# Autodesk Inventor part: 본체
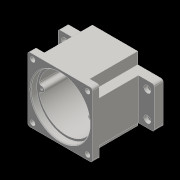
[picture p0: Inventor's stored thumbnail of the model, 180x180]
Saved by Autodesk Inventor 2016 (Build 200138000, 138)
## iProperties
Created: 2020-08
Part Number: 본체
Material: 일반
Document SubType Name: Modeling
Designer: User
Density: 1 g/cm^3
Appearance: 기본값
Author: User
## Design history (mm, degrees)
sketch "스케치1"
  geometry: L1 (47, 47)-(-47, 47); L2 (-47, 47)-(-47, -47); L3 (-47, -47)-(47, -47); L4 (47, -47)-(47, 47); L5 (47, 47)-(-47, -47); L6 (-47, 47)-(47, -47); 1 further point
  constraints: 12 end point, 2 midpoint, 2 parallel, 1 horizontal, 1 perpendicular
  dimensions: "d0" = 94 distance of L2.end L3.end; "d1" = 94 distance of L1.end L2.end
extrude "돌출1" new body sketch "스케치1" distance "d2" = 80; taper "d3" = 0 deg
sketch "스케치2"
  geometry: L1 (-70, -30)-(70, -30); L2 (70, -30)-(70, 30); L3 (70, 30)-(-70, 30); L4 (-70, 30)-(-70, -30); L5 (-70, -30)-(70, 30); L6 (70, -30)-(-70, 30); 1 further point
  constraints: 12 end point, 2 midpoint, 2 parallel, 1 horizontal, 1 perpendicular
  dimensions: "d4" = 60 distance of L1.end L2.end; "d5" = 140 distance of L2.end L3.end
extrude "돌출2" join sketch "스케치2" distance "d6" = 13; taper "d7" = 0 deg
sketch "스케치4"
  geometry: L1 (47, 47)-(-47, 47) reference; L2 (-47, 47)-(-33, 47); L3 (-33, 47)-(-33, 30); L4 (-33, 30)-(-47, 30); L5 (-47, 30)-(-47, 47); 1 further point
  constraints: 8 end point, 2 parallel, 1 horizontal, 1 perpendicular
  dimensions: "d8" = 17 distance of L2.end L3.end; "d9" = 14 distance of L3.end L4.end
extrude "돌출3" cut sketch "스케치4" distance "d10" = 70; taper "d11" = 0 deg
sketch "스케치5"
  geometry: L1 (-47, 47)-(-33, 47) reference; L2 (-47, 30)-(-47, 47) reference; C1 r 3.5 at (-40, 40); 1 further point
  constraints: 1 centre point
  dimensions: "d12" = 7 distance from line of L1 C1.centre; "d13" = 7 distance from line of C1.centre L2; "d14" = 7 diameter of C1
extrude "돌출4" cut sketch "스케치5" distance "d15" = 70; taper "d16" = 0 deg
sketch "스케치6"
  geometry: C1 r 27.5 at (0, 11); 1 further point
  constraints: 1 centre point, 1 vertical alignment
  dimensions: "d23" = 55 diameter of C1; "d24" = 11 distance of point (0, 0) C1.centre
extrude "돌출5" join sketch "스케치6" distance "d25" = 7; taper "d26" = 0 deg
sketch "스케치7"
  geometry: C1 r 27.5 at (0, 0) reference; C2 r 16 at (0, 0); 1 further point
  constraints: 1 centre point, 1 coincident
  dimensions: "d27" = 32 diameter of C2
extrude "돌출6" cut sketch "스케치7" distance "d28" = 9.1; taper "d29" = 0 deg
sketch "스케치8"
  geometry: C1 r 43 at (0, 0); 1 further point
  constraints: 1 centre point, 1 coincident
  dimensions: "d30" = 86 diameter of C1
extrude "돌출7" cut sketch "스케치8" distance "d31" = 9; taper "d32" = 0 deg
sketch "스케치9"
  geometry: C1 r 40 at (0, 0); 1 further point
  constraints: 1 centre point, 1 coincident
  dimensions: "d33" = 80 diameter of C1
extrude "돌출8" cut sketch "스케치9" distance "d34" = 62; taper "d35" = 0 deg
sketch "스케치10"
  geometry: C1 r 16 at (0, -11) reference; C2 r 21 at (0, -11); 1 further point
  constraints: 1 centre point, 1 coincident
  dimensions: "d36" = 42 diameter of C2
extrude "돌출9" join sketch "스케치10" distance "d37" = 7; taper "d38" = 0 deg
sketch "스케치11"
  geometry: L1 (-98, 0)-(98, 0) reference; L2 (0, -65.8)-(0, 65.8) reference; C1 r 15 at (0, 20); C2 r 21 at (0, -11) reference; 1 further point
  constraints: 1 centre point, 1 vertical alignment
  dimensions: "d39" = 20 distance from line of L1 C1.centre; "d40" = 30 diameter of C1
extrude "돌출10" join sketch "스케치11" distance "d41" = 7; taper "d42" = 0 deg
sketch "스케치15"
  geometry: L1 (-98, 0)-(98, 0) reference; L2 (0, -65.8)-(0, 65.8) reference; A1 r 4 centre (36, 0) between (36.19, 3.995) and (36.19, -3.995); A2 r 3 centre (36.333, -6.992) between (39.279, -7.559) and (36.19, -3.995); A3 r 3 centre (36.333, 6.992) between (36.19, 3.995) and (39.279, 7.559); A4 r 40 centre (0, 0) between (39.279, -7.559) and (39.279, 7.559) reference; 1 further point
  constraints: 8 point on circle, 5 tangent, 3 centre point, 1 horizontal alignment, 1 point on line
  dimensions: "d54" = 8 diameter of A1; "d55" = 6 diameter of A3; "d56" = 6 diameter of A2
extrude "돌출14" join sketch "스케치15" stored distance "d57" = 3; taper "d58" = 0 deg
sketch "스케치16"
  geometry: A1 r 4 centre (36, 0) between (36.19, 3.995) and (36.19, -3.995) reference; 2 further points
  constraints: 1 coincident
hole "구멍1" sketch "스케치16" at (36, 0) diameter "d59" = 3.242; stored, may be unused: countersink angle "d63" = 90 deg, drill point angle "d65" = 118 deg; dims "d60" = 7, "d61" = 4, "d62" = 2, "d64" = 9
sketch "스케치17"
  geometry: L1 (-98, 0)-(98, 0) reference; L2 (0, -65.8)-(0, 65.8) reference; L3 (47, -30)-(70, -30) reference; 3 further points
  dimensions: "d66" = 38 distance of point (60, 19) point (60, -19); "d67" = 60 distance from line of point (60, -19) L2; "d68" = 60 distance from line of L2 point (60, 19); "d69" = 11 distance from line of point (60, -19) L3
hole "구멍2" sketch "스케치17" at (60, -19), (60, 19) diameter "d70" = 4.5; stored, may be unused: countersink angle "d74" = 90 deg, drill point angle "d76" = 118 deg; dims "d71" = 7, "d72" = 10, "d73" = 5, "d75" = 20
chamfer "모따기1" distance "d77" = 0.8; stored, may be unused: second distance "d78" = 2, angle "d79" = 30 deg
fillet "모깎기1" dims "d83" = 3
chamfer "모따기5" distance "d91" = 1; stored, may be unused: second distance "d92" = 2, angle "d93" = 30 deg
sketch "스케치18"
  geometry: L1 (-77, -10)-(11, -10) reference; L2 (14, 57)-(14, 0) reference; 2 further points
  constraints: 1 other
  dimensions: "d94" = 40 distance from line of L1 point (-33, 30); "d95" = 47 distance from line of L2 point (-33, 30)
feature "엠보싱1" sketch "스케치18" dims "d96" = 0.5, "d97" = 0
sketch "스케치19"
  geometry: C1 r 17.5 at (0, -11); A1 r 21 centre (0, -11) between (-8.978, 7.984) and (8.978, 7.984) reference; A2 r 15 centre (0, 20) between (8.978, 7.984) and (-8.978, 7.984) reference; 1 further point
  constraints: 1 centre point, 1 coincident
  dimensions: "d98" = 35 diameter of C1
extrude "돌출15" cut sketch "스케치19" distance "d99" = 10; taper "d100" = 0 deg
sketch "스케치20"
  geometry: C1 r 17.5 at (0, 0) reference; C2 r 12.5 at (0, 0); 1 further point
  constraints: 1 centre point, 1 coincident
  dimensions: "d101" = 25 diameter of C2
extrude "돌출16" cut sketch "스케치20" distance "d102" = 10; taper "d103" = 0 deg
sketch "스케치21"
  geometry: C1 r 11 at (0, 20); A1 r 15 centre (0, 20) between (8.978, 7.984) and (-8.978, 7.984) reference; 1 further point
  constraints: 1 centre point, 1 coincident
  dimensions: "d104" = 22 diameter of C1
extrude "돌출17" cut sketch "스케치21" distance "d105" = 7; taper "d106" = 0 deg
sketch "스케치22"
  geometry: C1 r 11 at (0, 0) reference; C2 r 9.5 at (0, 0); 1 further point
  constraints: 1 centre point, 1 coincident
  dimensions: "d107" = 19 diameter of C2
extrude "돌출18" cut sketch "스케치22" distance "d108" = 3; taper "d109" = 0 deg
chamfer "모따기6" distance "d110" = 1; stored, may be unused: second distance "d111" = 2, angle "d112" = 30 deg
fillet "모깎기3" dims "d113" = 3
node "솔리드1"
mirror "대칭1"
mirror "대칭2"
pattern_linear "직사각형 패턴1" dims "d19" = 80
mirror "대칭3"
mirror "대칭4"
